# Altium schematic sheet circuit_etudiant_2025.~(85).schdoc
size A4; SheetNumber: 1; SheetTotal: 1; SPICEModelCacheTIKVTHVS: <root> / <DocumentId>TIKVTHVS</DocumentId> / <CacheFrame Number="0"> / <Model Name="ideal" Kind="ckt"> / <Text>.SUBCKT IDEAL 1 2 3 / EGAIN 3 0 1 2 1E5 / .ENDS</Text> / </Model> / </CacheFrame> / </root>
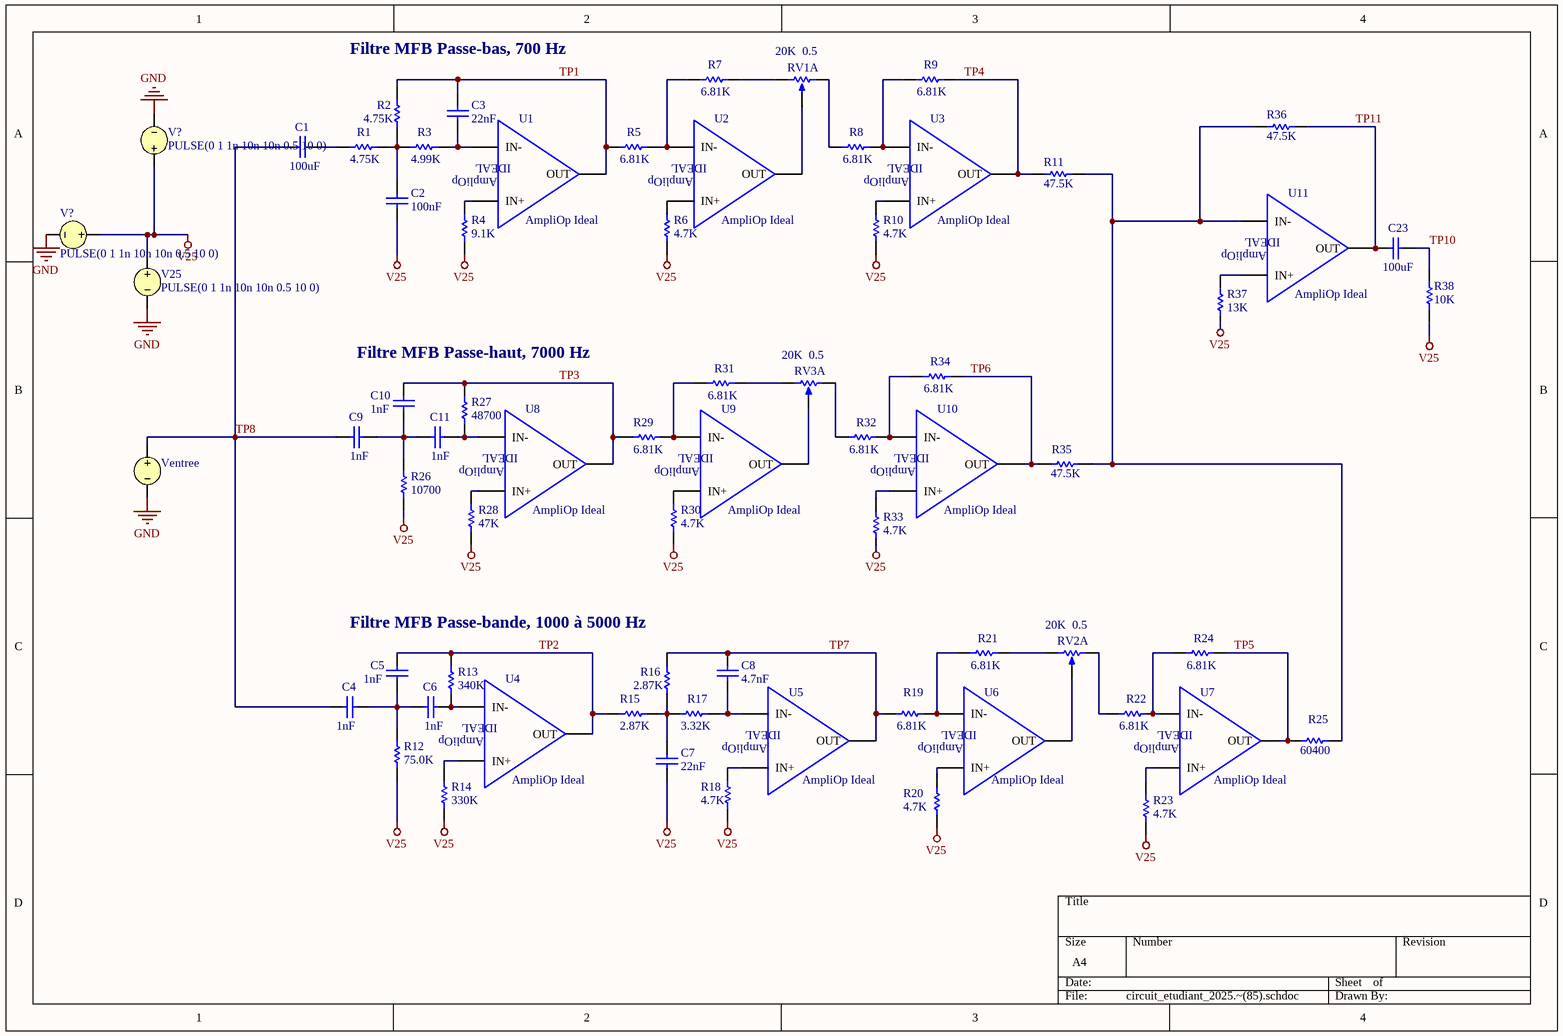
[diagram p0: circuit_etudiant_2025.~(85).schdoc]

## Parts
(Parts that share a designator on the sheet are numbered #1, #2 ... from top to bottom, then left to right.)
C1  value 100uF  [RAD-0.3]  (hidden comment: Cap)
C2  value 100nF  [RAD-0.3]  (hidden comment: Cap)
C3  value 22nF  [RAD-0.3]  (hidden comment: Cap)
C4  value 1nF  [RAD-0.3]  (hidden comment: Cap)
C5  value 1nF  [RAD-0.3]  (hidden comment: Cap)
C6  value 1nF  [RAD-0.3]  (hidden comment: Cap)
C7  value 22nF  [RAD-0.3]  (hidden comment: Cap)
C8  value 4.7nF  [RAD-0.3]  (hidden comment: Cap)
C9  value 1nF  [RAD-0.3]  (hidden comment: Cap)
C10  value 1nF  [RAD-0.3]  (hidden comment: Cap)
C11  value 1nF  [RAD-0.3]  (hidden comment: Cap)
C23  value 100uF  [RAD-0.3]  (hidden comment: Cap)
R1  value 4.75K  [AXIAL-0.3]  (hidden comment: Res1)
R2  value 4.75K  [AXIAL-0.3]  (hidden comment: Res1)
R3  value 4.99K  [AXIAL-0.3]  (hidden comment: Res1)
R4  value 9.1K  [AXIAL-0.3]  (hidden comment: Res1)
R5  value 6.81K  [AXIAL-0.3]  (hidden comment: Res1)
R6  value 4.7K  [AXIAL-0.3]  (hidden comment: Res1)
R7  value 6.81K  [AXIAL-0.3]  (hidden comment: Res1)
R8  value 6.81K  [AXIAL-0.3]  (hidden comment: Res1)
R9  value 6.81K  [AXIAL-0.3]  (hidden comment: Res1)
R10  value 4.7K  [AXIAL-0.3]  (hidden comment: Res1)
R11  value 47.5K  [AXIAL-0.3]  (hidden comment: Res1)
R12  value 75.0K  [AXIAL-0.3]  (hidden comment: Res1)
R13  value 340K  [AXIAL-0.3]  (hidden comment: Res1)
R14  value 330K  [AXIAL-0.3]  (hidden comment: Res1)
R15  value 2.87K  [AXIAL-0.3]  (hidden comment: Res1)
R16  value 2.87K  [AXIAL-0.3]  (hidden comment: Res1)
R17  value 3.32K  [AXIAL-0.3]  (hidden comment: Res1)
R18  value 4.7K  [AXIAL-0.3]  (hidden comment: Res1)
R19  value 6.81K  [AXIAL-0.3]  (hidden comment: Res1)
R20  value 4.7K  [AXIAL-0.3]  (hidden comment: Res1)
R21  value 6.81K  [AXIAL-0.3]  (hidden comment: Res1)
R22  value 6.81K  [AXIAL-0.3]  (hidden comment: Res1)
R23  value 4.7K  [AXIAL-0.3]  (hidden comment: Res1)
R24  value 6.81K  [AXIAL-0.3]  (hidden comment: Res1)
R25  value 60400  [AXIAL-0.3]  (hidden comment: Res1)
R26  value 10700  [AXIAL-0.3]  (hidden comment: Res1)
R27  value 48700  [AXIAL-0.3]  (hidden comment: Res1)
R28  value 47K  [AXIAL-0.3]  (hidden comment: Res1)
R29  value 6.81K  [AXIAL-0.3]  (hidden comment: Res1)
R30  value 4.7K  [AXIAL-0.3]  (hidden comment: Res1)
R31  value 6.81K  [AXIAL-0.3]  (hidden comment: Res1)
R32  value 6.81K  [AXIAL-0.3]  (hidden comment: Res1)
R33  value 4.7K  [AXIAL-0.3]  (hidden comment: Res1)
R34  value 6.81K  [AXIAL-0.3]  (hidden comment: Res1)
R35  value 47.5K  [AXIAL-0.3]  (hidden comment: Res1)
R36  value 47.5K  [AXIAL-0.3]  (hidden comment: Res1)
R37  value 13K  [AXIAL-0.3]  (hidden comment: Res1)
R38  value 10K  [AXIAL-0.3]  (hidden comment: Res1)
RV1A  value 20K  Set Position: 0.5  [VR5]  (hidden comment: RPot)
RV2A  value 20K  Set Position: 0.5  [VR5]  (hidden comment: RPot)
RV3A  value 20K  Set Position: 0.5  [VR5]  (hidden comment: RPot)
U1  AmpliOp Ideal
U2  AmpliOp Ideal
U3  AmpliOp Ideal
U4  AmpliOp Ideal
U5  AmpliOp Ideal
U6  AmpliOp Ideal
U7  AmpliOp Ideal
U8  AmpliOp Ideal
U9  AmpliOp Ideal
U10  AmpliOp Ideal
U11  AmpliOp Ideal
V25  PULSE(0 1 1n 10n 10n 0.5 10 0)
V?#1  PULSE(0 1 1n 10n 10n 0.5 10 0)
V?#2  PULSE(0 1 1n 10n 10n 0.5 10 0)
Ventree  SIN(0 1 1Meg 0 0 0)  (value not drawn)

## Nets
GND: V25.2 V?#1.2 V?#2.2 Ventree.2
V25: C2.2 C7.2 R4.2 R6.2 R10.2 R12.2 R14.2 R18.2 R20.2 R23.2 R26.2 R28.2 R30.2 R33.2 R37.2 R38.1 V25.1 V?#1.1 V?#2.1
TP1: C3.1 R2.1 R5.1 U1.3(OUT)
TP2: C5.1 R13.1 R15.1 U4.3(OUT)
TP3: C10.1 R27.1 R29.1 U8.3(OUT)
TP4: R9.2 R11.1 U3.3(OUT)
TP5: R24.2 R25.1 U7.3(OUT)
TP6: R34.2 R35.1 U10.3(OUT)
TP7: C8.1 R16.1 R19.1 U5.3(OUT)
TP8: C1.1 C4.1 C9.1 Ventree.1
TP10: C23.2 R38.2
TP11: C23.1 R36.2 U11.3(OUT)
NetC1_2: C1.2 R1.1
NetC2_1: C2.1 R1.2 R2.2 R3.1
NetC3_2: C3.2 R3.2 U1.2(IN-)
NetC4_2: C4.2 C5.2 C6.1 R12.1
NetC6_2: C6.2 R13.2 U4.2(IN-)
NetC7_1: C7.1 R15.2 R16.2 R17.1
NetC8_2: C8.2 R17.2 U5.2(IN-)
NetC9_2: C9.2 C10.2 C11.1 R26.1
NetC11_2: C11.2 R27.2 U8.2(IN-)
NetR4_1: R4.1 U1.1(IN+)
NetR5_2: R5.2 R7.1 U2.2(IN-)
NetR6_1: R6.1 U2.1(IN+)
NetR7_2: R7.2 RV1A.1(TOP)
NetR8_1: R8.1 RV1A.2(BOT)
NetR8_2: R8.2 R9.1 U3.2(IN-)
NetR10_1: R10.1 U3.1(IN+)
NetR11_2: R11.2 R25.2 R35.2 R36.1 U11.2(IN-)
NetR14_1: R14.1 U4.1(IN+)
NetR18_1: R18.1 U5.1(IN+)
NetR19_2: R19.2 R21.1 U6.2(IN-)
NetR20_1: R20.1 U6.1(IN+)
NetR21_2: R21.2 RV2A.1(TOP)
NetR22_1: R22.1 RV2A.2(BOT)
NetR22_2: R22.2 R24.1 U7.2(IN-)
NetR23_1: R23.1 U7.1(IN+)
NetR28_1: R28.1 U8.1(IN+)
NetR29_2: R29.2 R31.1 U9.2(IN-)
NetR30_1: R30.1 U9.1(IN+)
NetR31_2: R31.2 RV3A.1(TOP)
NetR32_1: R32.1 RV3A.2(BOT)
NetR32_2: R32.2 R34.1 U10.2(IN-)
NetR33_1: R33.1 U10.1(IN+)
NetR37_1: R37.1 U11.1(IN+)
NetRV1A_3: RV1A.3(TAP) U2.3(OUT)
NetRV2A_3: RV2A.3(TAP) U6.3(OUT)
NetRV3A_3: RV3A.3(TAP) U9.3(OUT)

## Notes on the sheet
- Filtre MFB Passe-bas, 700 Hz
- Filtre MFB Passe-haut, 7000 Hz
- Filtre MFB Passe-bande, 1000 à 5000 Hz

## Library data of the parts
C1-C11 C23 = Cap: Capacitor
R1-R38 = Res1: Resistor
RV1A RV2A RV3A = RPot: Potentiometer; Sim Note: Enter the Resistance value and the set point into parameter fields.
U1-U11 = AmpliOp_ideal
V25 V?#1 V?#2 = VSRC: Voltage Source; Note: PCB Footprint - Not required; AC Magnitude: 0; DC Magnitude: 1; Pulse Width: 0.5; Period: 10
Ventree = VSRC: Voltage Source; Note: PCB Footprint - Not required; AC Magnitude: 1; AC Phase: 0; DC Magnitude: 2.5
